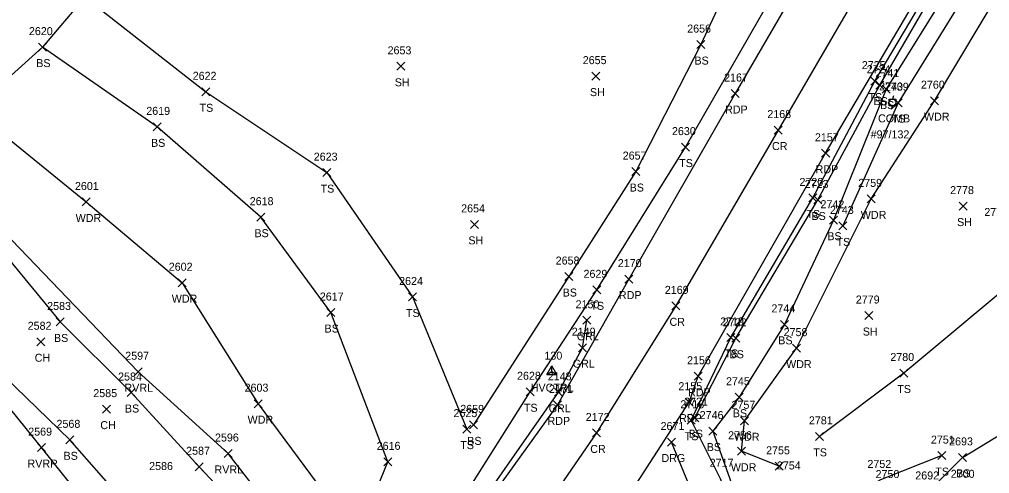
# Model space of a CAD drawing. Extents: x 1633660 to 1636532, y 388643 to 392631.
# Drawn here: x 1634668.1 to 1634910.5, y 389295.1 to 389408.7 of the extents above; entities that cross this region are included whole.
import ezdxf

# ---------------------------------------------------------------- set-up
doc = ezdxf.new("R2010")
doc.units = 0
for name, color, linetype in [('C_A', 7, 'Continuous'), ('C_I', 7, 'Continuous'), ('CPSM', 7, 'Continuous'), ('L_A', 7, 'Continuous'), ('L_I', 7, 'Continuous'), ('L_TIC', 7, 'Continuous'), ('LAWA', 7, 'Continuous'), ('LAWE', 7, 'Continuous'), ('LELB', 7, 'Continuous'), ('LSOGP', 7, 'Continuous'), ('P_A', 7, 'Continuous'), ('P_I', 7, 'Continuous'), ('P_TIC', 7, 'Continuous'), ('PET', 7, 'Continuous'), ('PRC', 7, 'Continuous'), ('R_A', 7, 'Continuous'), ('R_I', 7, 'Continuous'), ('R_TIC', 7, 'Continuous'), ('RDG', 7, 'Continuous'), ('RGR', 7, 'Continuous'), ('U_A', 7, 'Continuous'), ('U_C', 7, 'Continuous'), ('U_I', 7, 'Continuous'), ('UP', 7, 'Continuous')]:
    doc.layers.add(name, color=color, linetype=linetype)

msp = doc.modelspace()

# ---------------------------------------------------------------- linework, layer by layer
at = {"layer": 'CPSM'}
for p, q in [((1634799.91, 389319.91), (1634801.16, 389322.08)), ((1634802.41, 389319.91), (1634801.16, 389322.08)), ((1634801.16, 389320.63), (1634801.16, 389322.08)), ((1634799.91, 389319.91), (1634801.16, 389320.63)), ((1634799.91, 389319.91), (1634802.41, 389319.91)), ((1634801.16, 389320.63), (1634801.16, 389320.63)), ((1634801.16, 389320.63), (1634802.41, 389319.91))]:
    msp.add_line(p, q, dxfattribs=at)
at = {"layer": 'L_TIC'}
for points in [[(1634672.84, 389400.81), (1634674.84, 389402.81)], [(1634674.84, 389400.81), (1634672.84, 389402.81)], [(1634837.33, 389401.44), (1634839.33, 389403.44)], [(1634839.33, 389401.44), (1634837.33, 389403.44)], [(1634762.39, 389396.01), (1634764.39, 389398.01)], [(1634764.39, 389396.01), (1634762.39, 389398.01)], [(1634811.16, 389393.55), (1634813.16, 389395.55)], [(1634813.16, 389393.55), (1634811.16, 389395.55)], [(1634880.84, 389392.3), (1634882.84, 389394.3)], [(1634882.84, 389392.3), (1634880.84, 389394.3)], [(1634882.07, 389391.29), (1634884.07, 389393.29)], [(1634884.07, 389391.29), (1634882.07, 389393.29)], [(1634883.7, 389390.31), (1634885.7, 389392.31)], [(1634885.7, 389390.31), (1634883.7, 389392.31)], [(1634713.69, 389389.63), (1634715.69, 389391.63)], [(1634715.69, 389389.63), (1634713.69, 389391.63)], [(1634895.76, 389387.41), (1634897.76, 389389.41)], [(1634897.76, 389387.41), (1634895.76, 389389.41)], [(1634886.64, 389386.9), (1634888.64, 389388.9)], [(1634888.64, 389386.9), (1634886.64, 389388.9)], [(1634701.53, 389380.86), (1634703.53, 389382.86)], [(1634703.53, 389380.86), (1634701.53, 389382.86)], [(1634833.55, 389375.8), (1634835.55, 389377.8)], [(1634835.55, 389375.8), (1634833.55, 389377.8)], [(1634743.94, 389369.41), (1634745.94, 389371.41)], [(1634745.94, 389369.41), (1634743.94, 389371.41)], [(1634821.14, 389369.68), (1634823.14, 389371.68)], [(1634823.14, 389369.68), (1634821.14, 389371.68)], [(1634865.35, 389363.08), (1634867.35, 389365.08)], [(1634867.35, 389363.08), (1634865.35, 389365.08)], [(1634683.77, 389362.07), (1634685.77, 389364.07)], [(1634685.77, 389362.07), (1634683.77, 389364.07)], [(1634866.58, 389362.57), (1634868.58, 389364.57)], [(1634868.58, 389362.57), (1634866.58, 389364.57)], [(1634879.97, 389362.85), (1634881.97, 389364.85)], [(1634881.97, 389362.85), (1634879.97, 389364.85)], [(1634902.92, 389361.04), (1634904.92, 389363.04)], [(1634904.92, 389361.04), (1634902.92, 389363.04)], [(1634727.37, 389358.27), (1634729.37, 389360.27)], [(1634729.37, 389358.27), (1634727.37, 389360.27)], [(1634780.78, 389356.47), (1634782.78, 389358.47)], [(1634782.78, 389356.47), (1634780.78, 389358.47)], [(1634870.53, 389357.51), (1634872.53, 389359.51)], [(1634872.53, 389357.51), (1634870.53, 389359.51)], [(1634872.89, 389356.08), (1634874.89, 389358.08)], [(1634874.89, 389356.08), (1634872.89, 389358.08)], [(1634707.79, 389341.88), (1634709.79, 389343.88)], [(1634709.79, 389341.88), (1634707.79, 389343.88)], [(1634804.4, 389343.42), (1634806.4, 389345.42)], [(1634806.4, 389343.42), (1634804.4, 389345.42)], [(1634811.36, 389340.1), (1634813.36, 389342.1)], [(1634813.36, 389340.1), (1634811.36, 389342.1)], [(1634765.28, 389338.31), (1634767.28, 389340.31)], [(1634767.28, 389338.31), (1634765.28, 389340.31)], [(1634744.89, 389334.42), (1634746.89, 389336.42)], [(1634746.89, 389334.42), (1634744.89, 389336.42)], [(1634677.27, 389332.06), (1634679.27, 389334.06)], [(1634679.27, 389332.06), (1634677.27, 389334.06)], [(1634879.36, 389333.67), (1634881.36, 389335.67)], [(1634881.36, 389333.67), (1634879.36, 389335.67)], [(1634858.27, 389331.46), (1634860.27, 389333.46)], [(1634860.27, 389331.46), (1634858.27, 389333.46)], [(1634672.4, 389327.11), (1634674.4, 389329.11)], [(1634674.4, 389327.11), (1634672.4, 389329.11)], [(1634844.9, 389328.19), (1634846.9, 389330.19)], [(1634846.9, 389328.19), (1634844.9, 389330.19)], [(1634846.11, 389327.98), (1634848.11, 389329.98)], [(1634848.11, 389327.98), (1634846.11, 389329.98)], [(1634861.31, 389325.51), (1634863.31, 389327.51)], [(1634863.31, 389325.51), (1634861.31, 389327.51)], [(1634696.78, 389319.61), (1634698.78, 389321.61)], [(1634698.78, 389319.61), (1634696.78, 389321.61)], [(1634888.07, 389319.29), (1634890.07, 389321.29)], [(1634890.07, 389319.29), (1634888.07, 389321.29)], [(1634794.74, 389314.6), (1634796.74, 389316.6)], [(1634796.74, 389314.6), (1634794.74, 389316.6)], [(1634695, 389314.41), (1634697, 389316.41)], [(1634697, 389314.41), (1634695, 389316.41)], [(1634846.91, 389313.24), (1634848.91, 389315.24)], [(1634848.91, 389313.24), (1634846.91, 389315.24)], [(1634688.8, 389310.26), (1634690.8, 389312.26)], [(1634690.8, 389310.26), (1634688.8, 389312.26)], [(1634726.74, 389311.62), (1634728.74, 389313.62)], [(1634728.74, 389311.62), (1634726.74, 389313.62)], [(1634834.93, 389307.48), (1634836.93, 389309.48)], [(1634836.93, 389307.48), (1634834.93, 389309.48)], [(1634835.88, 389308.12), (1634837.88, 389310.12)], [(1634837.88, 389308.12), (1634835.88, 389310.12)], [(1634848.29, 389307.34), (1634850.29, 389309.34)], [(1634850.29, 389307.34), (1634848.29, 389309.34)], [(1634778.85, 389305.26), (1634780.85, 389307.26)], [(1634780.85, 389305.26), (1634778.85, 389307.26)], [(1634780.56, 389306.32), (1634782.56, 389308.32)], [(1634782.56, 389306.32), (1634780.56, 389308.32)], [(1634679.66, 389302.58), (1634681.66, 389304.58)], [(1634681.66, 389302.58), (1634679.66, 389304.58)], [(1634840.4, 389304.77), (1634842.4, 389306.77)], [(1634842.4, 389304.77), (1634840.4, 389306.77)], [(1634867.06, 389303.45), (1634869.06, 389305.45)], [(1634869.06, 389303.45), (1634867.06, 389305.45)], [(1634672.59, 389300.63), (1634674.59, 389302.63)], [(1634674.59, 389300.63), (1634672.59, 389302.63)], [(1634719.26, 389299.16), (1634721.26, 389301.16)], [(1634721.26, 389299.16), (1634719.26, 389301.16)], [(1634847.5, 389299.72), (1634849.5, 389301.72)], [(1634849.5, 389299.72), (1634847.5, 389301.72)], [(1634897.55, 389298.63), (1634899.55, 389300.63)], [(1634899.55, 389298.63), (1634897.55, 389300.63)], [(1634902.72, 389298.19), (1634904.72, 389300.19)], [(1634904.72, 389298.19), (1634902.72, 389300.19)], [(1634712, 389295.84), (1634714, 389297.84)], [(1634714, 389295.84), (1634712, 389297.84)], [(1634759.16, 389297.07), (1634761.16, 389299.07)], [(1634761.16, 389297.07), (1634759.16, 389299.07)], [(1634856.94, 389295.96), (1634858.94, 389297.96)], [(1634858.94, 389295.96), (1634856.94, 389297.96)]]:
    msp.add_lwpolyline(points, dxfattribs=at)
at = {"layer": 'LAWA'}
for points in [[(1634857.94, 389296.96), (1634848.5, 389300.72), (1634849.29, 389308.34), (1634862.31, 389326.51), (1634880.97, 389363.85), (1634896.76, 389388.41), (1634914.26, 389417.76), (1634933.85, 389453.8), (1634957.87, 389490.4)], [(1634656.41, 389386.08), (1634684.77, 389363.07), (1634708.79, 389342.88), (1634727.74, 389312.62), (1634749.11, 389283.63)]]:
    msp.add_lwpolyline(points, dxfattribs=at)
at = {"layer": 'LAWE'}
for points in [[(1634748.89, 389270.78), (1634735.19, 389280.87), (1634720.26, 389300.16), (1634697.78, 389320.61), (1634664.26, 389355.51), (1634647.22, 389374.92)], [(1634726.75, 389249.59), (1634713.25, 389262.22), (1634694.91, 389274.92), (1634673.59, 389301.63), (1634663.85, 389313.71), (1634641.14, 389330.24), (1634625.58, 389344.61)]]:
    msp.add_lwpolyline(points, dxfattribs=at)
at = {"layer": 'LELB'}
for points in [[(1634902.32, 389527.48), (1634878.86, 389484.98), (1634853.49, 389435.06), (1634838.33, 389402.44), (1634822.14, 389370.68), (1634805.4, 389344.42), (1634781.56, 389307.32)], [(1634760.29, 389263.27), (1634777.7, 389287.05), (1634795.74, 389315.6), (1634812.36, 389341.1), (1634834.55, 389376.8), (1634859.6, 389420.59), (1634884.98, 389473.48), (1634914.7, 389519.94)], [(1634853.67, 389266.92), (1634843.26, 389293.83), (1634835.93, 389308.48), (1634845.9, 389329.19), (1634866.35, 389364.08), (1634881.84, 389393.3), (1634902.23, 389427.8), (1634921.56, 389460.56), (1634945.17, 389499.39)], [(1634836.88, 389309.12), (1634847.11, 389328.98), (1634867.58, 389363.57), (1634883.07, 389392.29), (1634903.19, 389426.99), (1634922.04, 389459.89), (1634948, 389498.04), (1634923.75, 389458.93), (1634905.81, 389425.35), (1634884.7, 389391.31), (1634871.53, 389358.51), (1634859.27, 389332.46), (1634847.91, 389314.24), (1634841.4, 389305.77), (1634847.29, 389289.16), (1634855.14, 389270.43), (1634869.81, 389281.76), (1634885.38, 389291.02)], [(1634950.98, 389495.12), (1634937.63, 389472.92), (1634927.6, 389456.09), (1634908.84, 389422.13), (1634887.64, 389387.9), (1634873.89, 389357.08)], [(1634684.41, 389414.41), (1634714.69, 389390.63), (1634744.94, 389370.41), (1634766.28, 389339.31), (1634779.85, 389306.26)], [(1634758.79, 389267.89), (1634752.88, 389275.17), (1634753.6, 389281.88), (1634760.16, 389298.07), (1634745.89, 389335.42), (1634728.37, 389359.27), (1634702.53, 389381.86), (1634673.84, 389401.81)], [(1635032.21, 389403.07), (1635007.58, 389384.86), (1634948.96, 389359.77), (1634920.67, 389346.56), (1634889.07, 389320.29), (1634868.06, 389304.45)], [(1634641.71, 389371.13), (1634664.46, 389349.91), (1634678.27, 389333.06), (1634696, 389315.41), (1634713, 389296.84), (1634727.52, 389281.42), (1634745.22, 389266.89), (1634752.92, 389261.93)], [(1634742.97, 389244.48), (1634736.28, 389256.06), (1634722.01, 389268.8), (1634707.38, 389278.77), (1634697.7, 389284.25), (1634680.66, 389303.58), (1634664.36, 389319.39), (1634645.08, 389331.2), (1634628.27, 389346.62)], [(1634928.63, 389269.14), (1634907.52, 389272.61), (1634904.9, 389276.76), (1634895.25, 389290.67), (1634903.72, 389299.19), (1634934.18, 389317.7), (1634977.92, 389336.59)], [(1634898.55, 389299.63), (1634883.26, 389293.55), (1634859.85, 389280.29), (1634860.63, 389293.16)]]:
    msp.add_lwpolyline(points, dxfattribs=at)
at = {"layer": 'LSOGP'}
msp.add_lwpolyline([(1634684.41, 389414.41), (1634673.84, 389401.81), (1634656.41, 389386.08)], dxfattribs=at)
at = {"layer": 'P_TIC'}
for points in [[(1634845.92, 389389.2), (1634847.92, 389391.2)], [(1634847.92, 389389.2), (1634845.92, 389391.2)], [(1634856.72, 389380.06), (1634858.72, 389382.06)], [(1634858.72, 389380.06), (1634856.72, 389382.06)], [(1634868.56, 389374.26), (1634870.56, 389376.26)], [(1634870.56, 389374.26), (1634868.56, 389376.26)], [(1634819.4, 389342.78), (1634821.4, 389344.78)], [(1634821.4, 389342.78), (1634819.4, 389344.78)], [(1634831.11, 389336.09), (1634833.11, 389338.09)], [(1634833.11, 389336.09), (1634831.11, 389338.09)], [(1634836.67, 389318.49), (1634838.67, 389320.49)], [(1634838.67, 389318.49), (1634836.67, 389320.49)], [(1634801.56, 389311.32), (1634803.56, 389313.32)], [(1634803.56, 389311.32), (1634801.56, 389313.32)], [(1634834.45, 389312), (1634836.45, 389314)], [(1634836.45, 389312), (1634834.45, 389314)], [(1634811.29, 389304.3), (1634813.29, 389306.3)], [(1634813.29, 389304.3), (1634811.29, 389306.3)]]:
    msp.add_lwpolyline(points, dxfattribs=at)
at = {"layer": 'PET'}
for points in [[(1634921, 389515.03), (1634899.8, 389480.53), (1634874.19, 389437.17), (1634846.92, 389390.2), (1634820.4, 389343.78), (1634802.56, 389312.32), (1634782.67, 389284.65), (1634768.75, 389267.29)], [(1634759.68, 389257.14), (1634768.68, 389246.68), (1634778.86, 389234.44), (1634802.84, 389262.52), (1634835.45, 389313), (1634837.67, 389319.49), (1634869.56, 389375.26), (1634896.66, 389421.5), (1634916.95, 389456.15), (1634943.65, 389500.19)]]:
    msp.add_lwpolyline(points, dxfattribs=at)
at = {"layer": 'PRC'}
msp.add_lwpolyline([(1634932, 389507.76), (1634911.04, 389472.8), (1634886.74, 389431.16), (1634857.72, 389381.06), (1634832.11, 389337.09), (1634812.29, 389305.3), (1634793.24, 389277.6), (1634779.17, 389259.21), (1634770.35, 389248.3)], dxfattribs=at)
at = {"layer": 'R_TIC'}
for points in [[(1634808.84, 389332.48), (1634810.84, 389334.48)], [(1634810.84, 389332.48), (1634808.84, 389334.48)], [(1634807.81, 389325.63), (1634809.81, 389327.63)], [(1634809.81, 389325.63), (1634807.81, 389327.63)], [(1634801.8, 389314.46), (1634803.8, 389316.46)], [(1634803.8, 389314.46), (1634801.8, 389316.46)], [(1634830.04, 389302.03), (1634832.04, 389304.03)], [(1634832.04, 389302.03), (1634830.04, 389304.03)]]:
    msp.add_lwpolyline(points, dxfattribs=at)
at = {"layer": 'RDG'}
msp.add_lwpolyline([(1634882.02, 389178.69), (1634870.53, 389207.32), (1634859.71, 389234.78), (1634848.9, 389265.96), (1634837.23, 389287.95), (1634831.04, 389303.03)], dxfattribs=at)
at = {"layer": 'RGR'}
msp.add_lwpolyline([(1634760.39, 389258.9), (1634777.73, 389279.59), (1634802.8, 389315.46), (1634808.81, 389326.63), (1634809.84, 389333.48)], dxfattribs=at)
at = {"layer": 'UP'}
for p, q in [((1634886.51, 389389.64), (1634886.26, 389388.81)), ((1634885.43, 389387.14), (1634885.43, 389388.81)), ((1634885.43, 389388.81), (1634887.1, 389388.81)), ((1634887.1, 389387.14), (1634885.43, 389387.14)), ((1634886.01, 389386.31), (1634886.26, 389387.14)), ((1634886.26, 389387.98), (1634886.26, 389387.98)), ((1634887.1, 389388.81), (1634887.1, 389387.14))]:
    msp.add_line(p, q, dxfattribs=at)
msp.add_circle((1634886.26, 389387.98), 0.833, dxfattribs=at)

# ---------------------------------------------------------------- texts
at = {"layer": 'C_A'}
msp.add_text('HVCTRL', height=2, dxfattribs=at).set_placement((1634795.86, 389315.63))
at = {"layer": 'C_I'}
msp.add_text('130', height=2, dxfattribs=at).set_placement((1634799.28, 389323.63))
at = {"layer": 'L_A'}
for s, p in [('BS', (1634836.77, 389397.44)), ('BS', (1634672.28, 389396.81)), ('SH', (1634761.88, 389392.01)), ('SH', (1634810.65, 389389.55)), ('TS', (1634880.25, 389388.3)), ('BS', (1634881.51, 389387.29)), ('TS', (1634713.1, 389385.63)), ('BS', (1634883.14, 389386.31)), ('TS', (1634886.05, 389382.9)), ('WDR', (1634894.12, 389383.41)), ('BS', (1634700.97, 389376.86)), ('TS', (1634832.96, 389371.8)), ('BS', (1634820.58, 389365.68)), ('TS', (1634743.35, 389365.41)), ('TS', (1634864.76, 389359.08)), ('BS', (1634866.02, 389358.57)), ('WDR', (1634878.34, 389358.85)), ('WDR', (1634682.13, 389358.07)), ('SH', (1634902.41, 389357.04)), ('BS', (1634726.81, 389354.27)), ('BS', (1634869.97, 389353.51)), ('SH', (1634780.27, 389352.47)), ('TS', (1634872.29, 389352.08)), ('BS', (1634803.84, 389339.42)), ('WDR', (1634706.15, 389337.88)), ('TS', (1634764.69, 389334.31)), ('TS', (1634810.77, 389336.1)), ('BS', (1634744.33, 389330.42)), ('SH', (1634878.84, 389329.67)), ('BS', (1634676.71, 389328.06)), ('BS', (1634857.72, 389327.46)), ('CH', (1634671.89, 389323.11)), ('TS', (1634844.31, 389324.19)), ('BS', (1634845.55, 389323.98)), ('WDR', (1634859.67, 389321.51)), ('RVRL', (1634694.34, 389315.61)), ('TS', (1634887.47, 389315.29)), ('BS', (1634694.44, 389310.41)), ('TS', (1634794.15, 389310.6)), ('WDR', (1634725.1, 389307.62)), ('BS', (1634846.35, 389309.24)), ('CH', (1634688.29, 389306.26)), ('TS', (1634834.34, 389303.48)), ('BS', (1634835.32, 389304.12)), ('WDR', (1634846.65, 389303.34)), ('TS', (1634778.26, 389301.26)), ('BS', (1634780, 389302.32)), ('BS', (1634839.84, 389300.77)), ('BS', (1634679.1, 389298.58)), ('TS', (1634866.47, 389299.45)), ('RVRR', (1634670.1, 389296.63)), ('RVRL', (1634716.83, 389295.16)), ('WDR', (1634845.86, 389295.72)), ('TS', (1634896.96, 389294.63)), ('BS', (1634902.16, 389294.19))]:
    msp.add_text(s, height=2, dxfattribs=at).set_placement(p)
at = {"layer": 'L_I'}
for s, p in [('2620', (1634670.45, 389404.81)), ('2656', (1634834.96, 389405.44)), ('2653', (1634760.08, 389400.01)), ('2655', (1634808.85, 389397.55)), ('2725', (1634878.58, 389396.3)), ('2724', (1634879.81, 389395.29)), ('2622', (1634711.38, 389393.63)), ('2741', (1634882.01, 389394.31)), ('2739', (1634884.37, 389390.9)), ('2760', (1634893.37, 389391.41)), ('2619', (1634699.78, 389384.86)), ('2630', (1634831.15, 389379.8)), ('2623', (1634741.63, 389373.41)), ('2657', (1634818.84, 389373.68)), ('2601', (1634681.95, 389366.07)), ('2720', (1634863.01, 389367.08)), ('2723', (1634864.32, 389366.57)), ('2759', (1634877.71, 389366.85)), ('2778', (1634900.66, 389365.04)), ('2618', (1634725.63, 389362.27)), ('2742', (1634868.27, 389361.51)), ('2654', (1634778.47, 389360.47)), ('2743', (1634870.63, 389360.08)), ('2777', (1634909.21, 389359.57)), ('2658', (1634802.09, 389347.42)), ('2602', (1634705.4, 389345.88)), ('2629', (1634809.05, 389344.1)), ('2624', (1634762.97, 389342.31)), ('2617', (1634743.15, 389338.42)), ('2779', (1634877.09, 389337.67)), ('2583', (1634675.01, 389336.06)), ('2744', (1634856.01, 389335.46)), ('2719', (1634843.2, 389332.19)), ('2722', (1634843.85, 389331.98)), ('2582', (1634670.14, 389331.11)), ('2758', (1634859.05, 389329.51)), ('2597', (1634694.52, 389323.61)), ('2780', (1634885.72, 389323.29)), ('2584', (1634692.74, 389318.41)), ('2628', (1634792.43, 389318.6)), ('2745', (1634844.65, 389317.24)), ('2603', (1634724.35, 389315.62)), ('2585', (1634686.54, 389314.26)), ('2721', (1634834.19, 389312.12)), ('2659', (1634778.24, 389310.32)), ('2718', (1634833.24, 389311.48)), ('2757', (1634846.03, 389311.34)), ('2625', (1634776.55, 389309.26)), ('2746', (1634838.08, 389308.77)), ('2781', (1634865.37, 389307.45)), ('2568', (1634677.35, 389306.58)), ('2569', (1634670.28, 389304.63)), ('2596', (1634716.95, 389303.16)), ('2756', (1634845.18, 389303.72)), ('2751', (1634895.86, 389302.63)), ('2616', (1634757.36, 389301.07)), ('2693', (1634900.41, 389302.19)), ('2587', (1634709.74, 389299.84)), ('2755', (1634854.68, 389299.96)), ('2586', (1634700.5, 389296.02)), ('2717', (1634840.57, 389296.83)), ('2754', (1634857.37, 389296.16)), ('2752', (1634880, 389296.55)), ('2750', (1634882.03, 389294.02)), ('2692', (1634891.95, 389293.67)), ('2700', (1634900.82, 389294.08))]:
    msp.add_text(s, height=2, dxfattribs=at).set_placement(p)
at = {"layer": 'P_A'}
for s, p in [('RDP', (1634844.41, 389385.2)), ('CR', (1634856.15, 389376.06)), ('RDP', (1634867.05, 389370.26)), ('RDP', (1634817.89, 389338.78)), ('CR', (1634830.54, 389332.09)), ('RDP', (1634835.16, 389314.49)), ('RDP', (1634800.05, 389307.32)), ('RDP', (1634832.94, 389308)), ('CR', (1634810.73, 389300.3))]:
    msp.add_text(s, height=2, dxfattribs=at).set_placement(p)
at = {"layer": 'P_I'}
for s, p in [('2167', (1634844.18, 389393.2)), ('2168', (1634854.98, 389384.06)), ('2157', (1634866.87, 389378.26)), ('2170', (1634817.62, 389346.78)), ('2169', (1634829.36, 389340.09)), ('2156', (1634834.92, 389322.49)), ('2171', (1634800.43, 389315.32)), ('2155', (1634832.76, 389316)), ('2172', (1634809.6, 389308.3))]:
    msp.add_text(s, height=2, dxfattribs=at).set_placement(p)
at = {"layer": 'R_A'}
for s, p in [('GRL', (1634807.38, 389328.48)), ('GRL', (1634806.36, 389321.63)), ('GRL', (1634800.34, 389310.46)), ('DRG', (1634828.53, 389298.03))]:
    msp.add_text(s, height=2, dxfattribs=at).set_placement(p)
at = {"layer": 'R_I'}
for s, p in [('2150', (1634807.06, 389336.48)), ('2149', (1634806.11, 389329.63)), ('2148', (1634800.11, 389318.46)), ('2671', (1634828.3, 389306.03))]:
    msp.add_text(s, height=2, dxfattribs=at).set_placement(p)
at = {"layer": 'U_A'}
msp.add_text('COMB', height=2, dxfattribs=at).set_placement((1634882.65, 389382.98))
at = {"layer": 'U_C'}
msp.add_text('#97/132', height=2, dxfattribs=at).set_placement((1634880.8, 389378.98))
at = {"layer": 'U_I'}
msp.add_text('2740', height=2, dxfattribs=at).set_placement((1634882.92, 389390.98))

doc.saveas('drawing.dxf')
